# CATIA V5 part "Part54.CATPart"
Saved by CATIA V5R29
Part number: spur gear_iso_ISO - Spur gear 0.5M 40T 20PA 7FW ---S40A75H50L16.0N
Revision: ANY
Definition: UNKNOWN
Nomenclature: spur gear_iso_ISO - Spur gear 0.5M 40T 20PA 7FW ---S40A75H50L16.0N
Source: Unknown
Bounding box of the stored display mesh (mm): x 0 to 7, y -10.479 to 10.479, z -10.479 to 10.479
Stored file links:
  C:\Users\Administrator\Desktop\프로젝트\Gripper\Part54.CATPart
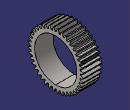
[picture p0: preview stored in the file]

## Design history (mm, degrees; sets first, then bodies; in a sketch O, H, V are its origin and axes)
Body1 "Bore" (main body)
  Solid1: solid without history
